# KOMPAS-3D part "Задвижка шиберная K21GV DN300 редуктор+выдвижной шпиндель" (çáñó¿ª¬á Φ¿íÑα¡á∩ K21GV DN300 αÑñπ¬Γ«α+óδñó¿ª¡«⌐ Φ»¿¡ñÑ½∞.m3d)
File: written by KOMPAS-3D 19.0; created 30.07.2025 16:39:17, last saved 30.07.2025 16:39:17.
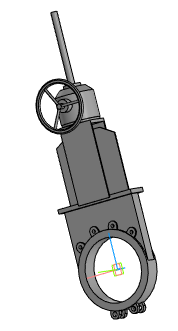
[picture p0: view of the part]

Document properties: Полное имя файла: Задвижка шиберная K21GV DN300 редуктор+выдвижной шпиндель.a3d

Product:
- Part/product: Задвижка шиберная K21GV DN300 редуктор+выдвижной шпиндель
    Масса: 103.573

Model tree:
1. Операция без истории:1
